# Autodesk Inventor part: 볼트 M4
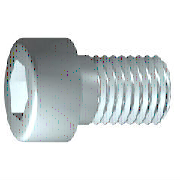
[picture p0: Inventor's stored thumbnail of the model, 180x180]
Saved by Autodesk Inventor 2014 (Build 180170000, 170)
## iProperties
IsCustomPart: 0
Created: 2012-02
Part Number: 볼트 M4
Material: 스테인리스강
Description: 6각 소켓 머리 캡 나사
Document SubType Name: Modeling
Standard: ISO 4762
Designer: mduedu
Standard Revision: Fourth edition 2004-03-01
Standards Organization: ISO
Language: ko-KR
Size Designation: M4 x 12
Categories: <MemberInstance><Categories><Category DisplayName="조임쇠" InternalName="e4da775c-781d-43d5-af7c-5136215cf5a6" Mnemonic="FSTN"><Category DisplayName="볼트" InternalN
Density: 8.08 g/cm^3
Appearance: 반광택
Author: mduedu
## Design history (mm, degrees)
sketch "스케치1"
  geometry: L1 (-1, 0)-(12, 0); L2 (12, 0)-(12, 2); L3 (12, 2)-(1.75, 2); L4 (1.75, 2)-(1.32, 2); L5 (1.32, 2)-(0, 2); L6 (0, 2)-(0, 3.5); L7 (0, 3.5)-(-4, 3.5); L8 (-4, 3.5)-(-4, 1.732); L9 (-4, 1.732)-(-2, 1.732); L10 (-2, 1.732)-(-1, 0); L11 (-7.2, 0)-(15.2, 0) reference; L12 (0, -0.7)-(0, 4.2) reference; L13 (1.75, 2)-(0, 2)
  constraints: 22 end point, 6 parallel, 2 collinear, 2 perpendicular, 1 horizontal, 1 point on line
  dimensions: "d1" = 10.25 distance from line of L3.end L2 (= GEL); "d2" = 0.42952 distance of L4.end L3.end (computed from GAL); "d3" = 4 distance between parallel lines of L8 L6 (= KOH); "d4" = 2 distance of L8.end L9.end (= INTI); "d5" = 60 deg angle of L10 L1; "d6" = 4 diameter of L3 L1 (= GD); "d7" = 4 diameter of L5 L1 (= BDM); "d8" = 3.4641 diameter of L9 L1 (= 1.1547 x SW); "d9" = 7 diameter of L7 L1 (= KOD); "d26" = 12 distance between parallel lines of L12 L2 (= NLG)
revolve "본체" sketch "스케치1" stored, may be unused: angle "d10" = 90 deg
sketch "스케치2"
  geometry: L1 (0, -4.9)-(0, 4.9) reference; L2 (-4.9, 0)-(4.9, 0) reference; L3 (1.732, 0)-(0.866, -1.5); L4 (0.866, -1.5)-(-0.866, -1.5); L5 (-0.866, -1.5)-(-1.732, 0); L6 (-1.732, 0)-(-0.866, 1.5); L7 (-0.866, 1.5)-(0.866, 1.5); L8 (0.866, 1.5)-(1.732, 0); 2 further points
  constraints: 12 end point, 1 coincident, 1 horizontal alignment, 1 point on line, 12 other
extrude "슬롯" join sketch "스케치2" stored distance "d11" = 10; taper "d12" = 0 deg
workplane "Work Plane1"
fillet "Fillet2" dims "d30" = 0.1 (= R)
body "Solid1"
fillet "모깎기1" dims "d17" = 0.4 (= RR)
feature "스레드" dims "d13" = 10.25 (= GEL), "d14" = 0
chamfer "모따기1" distance "d15" = 0.42941 (= -0.5 x SPD + 0.5 x GD); stored, may be unused: second distance "d16" = 0.42941 (= GUL), angle "d27" = 45 deg
other parameters: "GD" = 4 [user parameter; used in 2 equation terms], "NLG" = 12 [user parameter; used in 1 equation term], "GEL" = 10.25 [user parameter; used in 2 equation terms], "KOD" = 7 [user parameter; used in 1 equation term], "KOH" = 4 [user parameter; used in 1 equation term], "INTI" = 2 [user parameter; used in 1 equation term], "GAL" = 0.42941 (= 0.61345 x PTC) [user parameter; used in 1 equation term], "GUL" = 0.42941 (= 0.61345 x PTC) [user parameter; used in 1 equation term], "BDM" = 4 (= NND) [user parameter; used in 1 equation term], "SW" = 3 [user parameter; used in 2 equation terms], "RR" = 0.4 [user parameter; used in 1 equation term], "SPD" = 3.14117 (= NND - 1.2269 x PTC) [user parameter; used in 1 equation term], "d19" = 0, "d28" = 0, "d29" = 0, "R" = 0.1 [user parameter; used in 1 equation term], "TOA" = 30 deg [user parameter], "GD1" = 3.14117 (= THREADDIA - 1.2269 x PTC) [user parameter], "THREADDIA" = 4 [user parameter; used in 1 equation term], "FAWI" = 45 deg [user parameter], "TPU" = 14.28571 (computed from PTC) [user parameter], "PTC" = 0.7 [user parameter; used in 5 equation terms], "NND" = 4 [user parameter; used in 2 equation terms], "E0" = 3.465 (= 1.155 x SW) [user parameter]
